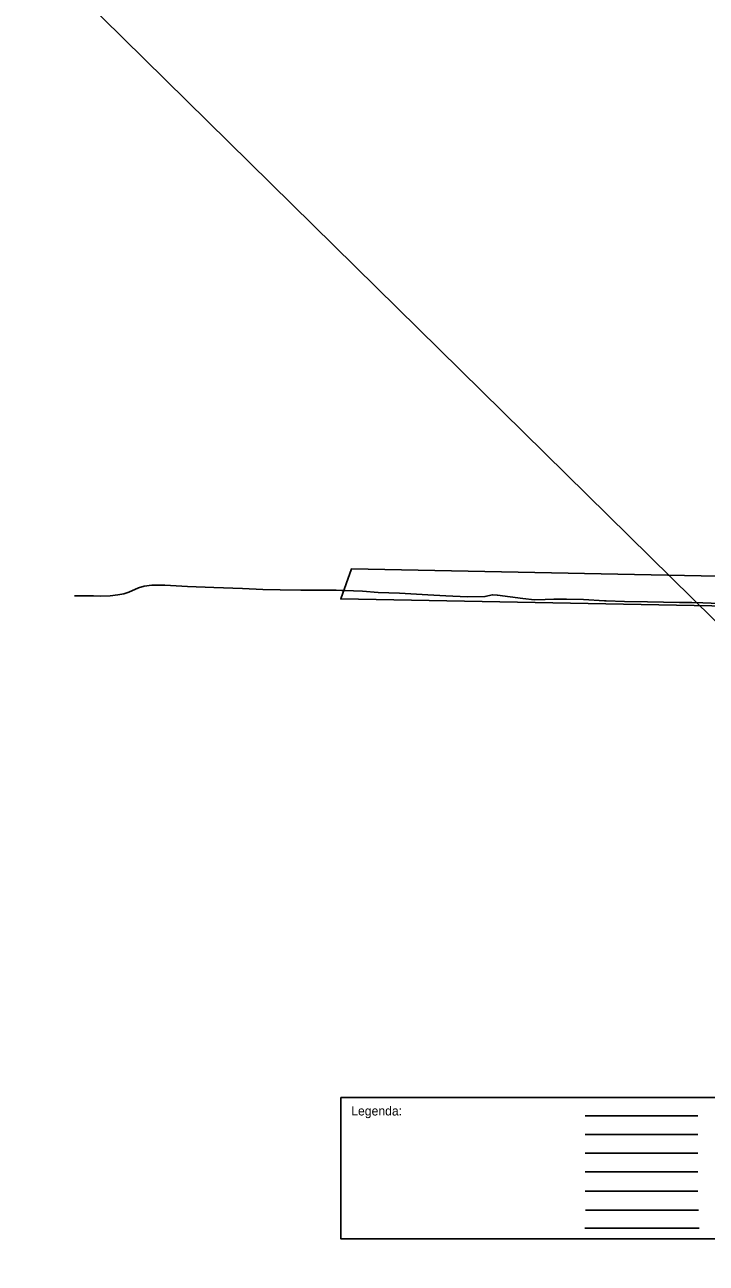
# Model space of a CAD drawing. Extents: x -880692 to -847963, y -1067899 to -1035686.
# Drawn here: x -852194 to -851073, y -1065908 to -1063872 of the extents above; entities that cross this region are included whole.
import ezdxf

# ---------------------------------------------------------------- set-up
doc = ezdxf.new("R2010")
doc.units = 0
for name, color, linetype in [('Vrstva 1', 7, 'Continuous'), ('Vrstva 5', 7, 'Continuous'), ('Vrstva 6', 7, 'Continuous'), ('Vrstva 63', 7, 'Continuous')]:
    doc.layers.add(name, color=color, linetype=linetype)

msp = doc.modelspace()

# ---------------------------------------------------------------- linework, layer by layer
at = {"layer": 'Vrstva 1'}
for p, q in [((-851272.658, -1065665.495), (-851087.249, -1065665.495)), ((-851272.658, -1065696.222), (-851087.249, -1065696.222)), ((-851272.658, -1065726.949), (-851087.249, -1065726.949)), ((-851272.658, -1065757.676), (-851087.249, -1065757.676)), ((-851272.658, -1065789.071), (-851087.249, -1065789.071)), ((-851271.738, -1065820.55), (-851086.329, -1065820.55)), ((-851272.908, -1065849.989), (-851084.901, -1065849.989))]:
    msp.add_line(p, q, dxfattribs=at)
for points in [[(-852111.96, -1064810.91), (-852080.6, -1064811.1), (-852069.31, -1064811.27), (-852053.56, -1064810.8), (-852040.95, -1064809.37), (-852031.11, -1064807.33), (-852022.5, -1064804.63), (-852006.97, -1064797.44), (-851997.66, -1064794.77), (-851984.98, -1064793.13), (-851963.42, -1064793.53), (-851926, -1064795.69), (-851883.07, -1064797.39), (-851835.81, -1064798.59), (-851802.29, -1064800.37), (-851774.1, -1064801.05), (-851739.97, -1064801.72), (-851711.39, -1064801.6), (-851681.68, -1064801.43), (-851672.23, -1064801.95)], [(-851672.23, -1064801.95), (-851666.93, -1064802.25), (-851653.07, -1064802.65), (-851638.56, -1064803.09), (-851612.74, -1064805.51), (-851577.68, -1064806.71), (-851530.97, -1064809.1), (-851501.75, -1064810.79), (-851466.62, -1064812.43), (-851437.24, -1064812.2), (-851424.56, -1064809.19), (-851424.11, -1064809.21), (-851417.29, -1064809.57), (-851416.37, -1064809.56), (-851374.95, -1064815.16), (-851355.48, -1064817.16), (-851338.32, -1064816.92), (-851324.08, -1064816.34), (-851302.93, -1064816.57), (-851274.92, -1064816.93), (-851240.45, -1064818.83)], [(-851653.07, -1064802.65), (-851638.56, -1064803.09)], [(-851424.11, -1064809.21), (-851417.29, -1064809.57)], [(-851240.45, -1064818.83), (-851238.61, -1064818.94), (-851237.95, -1064818.96)], [(-851237.95, -1064818.96), (-851207.67, -1064820.05), (-851169.69, -1064820.87), (-851117.44, -1064821.86), (-851096.82, -1064822), (-851079.13, -1064822.16), (-851051.81, -1064823.21), (-851020.06, -1064824.95), (-851001.01, -1064826.29)]]:
    msp.add_lwpolyline(points, dxfattribs=at)
msp.add_lwpolyline([(-851674.206, -1065635.449), (-850454.186, -1065635.449), (-850454.186, -1065867.518), (-851674.206, -1065867.518)], close=True, dxfattribs=at)
at = {"layer": 'Vrstva 5'}
msp.add_lwpolyline([(-880691.98, -1035685.98), (-847962.88, -1067898.87)], dxfattribs=at)
at = {"layer": 'Vrstva 6'}
for points in [[(-852111.96, -1064810.91), (-852080.6, -1064811.1), (-852069.31, -1064811.27), (-852053.56, -1064810.8), (-852040.95, -1064809.37), (-852031.11, -1064807.33), (-852022.5, -1064804.63), (-852006.97, -1064797.44), (-851997.66, -1064794.77), (-851984.98, -1064793.13), (-851963.42, -1064793.53), (-851926, -1064795.69), (-851883.07, -1064797.39), (-851835.81, -1064798.59), (-851802.29, -1064800.37), (-851774.1, -1064801.05), (-851739.97, -1064801.72), (-851711.39, -1064801.6), (-851681.68, -1064801.43), (-851672.23, -1064801.95)], [(-851672.23, -1064801.95), (-851666.93, -1064802.25), (-851653.07, -1064802.65), (-851638.56, -1064803.09), (-851612.74, -1064805.51), (-851577.68, -1064806.71), (-851530.97, -1064809.1), (-851501.75, -1064810.79), (-851466.62, -1064812.43), (-851437.24, -1064812.2), (-851424.56, -1064809.19), (-851424.11, -1064809.21), (-851417.29, -1064809.57), (-851416.37, -1064809.56), (-851374.95, -1064815.16), (-851355.48, -1064817.16), (-851338.32, -1064816.92), (-851324.08, -1064816.34), (-851302.93, -1064816.57), (-851274.92, -1064816.93), (-851240.45, -1064818.83)], [(-851240.45, -1064818.83), (-851238.61, -1064818.94), (-851237.95, -1064818.96)], [(-851237.95, -1064818.96), (-851207.67, -1064820.05), (-851169.69, -1064820.87), (-851117.44, -1064821.86), (-851096.82, -1064822), (-851079.13, -1064822.16), (-851051.81, -1064823.21), (-851020.06, -1064824.95), (-851001.01, -1064826.29)]]:
    msp.add_lwpolyline(points, dxfattribs=at)
at = {"layer": 'Vrstva 63'}
msp.add_lwpolyline([(-849493.378, -1064809.971), (-851656.346, -1064766.315), (-851674.206, -1064815.924), (-851035.237, -1064827.831), (-850578.831, -1064839.737), (-849947.799, -1064855.612), (-849491.393, -1064867.518), (-849493.378, -1064809.971)], close=True, dxfattribs=at)

# ---------------------------------------------------------------- texts
at = {"layer": 'Vrstva 1'}
msp.add_text('Legenda:', height=15, dxfattribs=at).set_placement((-851657.049, -1065664.932))

doc.saveas('drawing.dxf')
